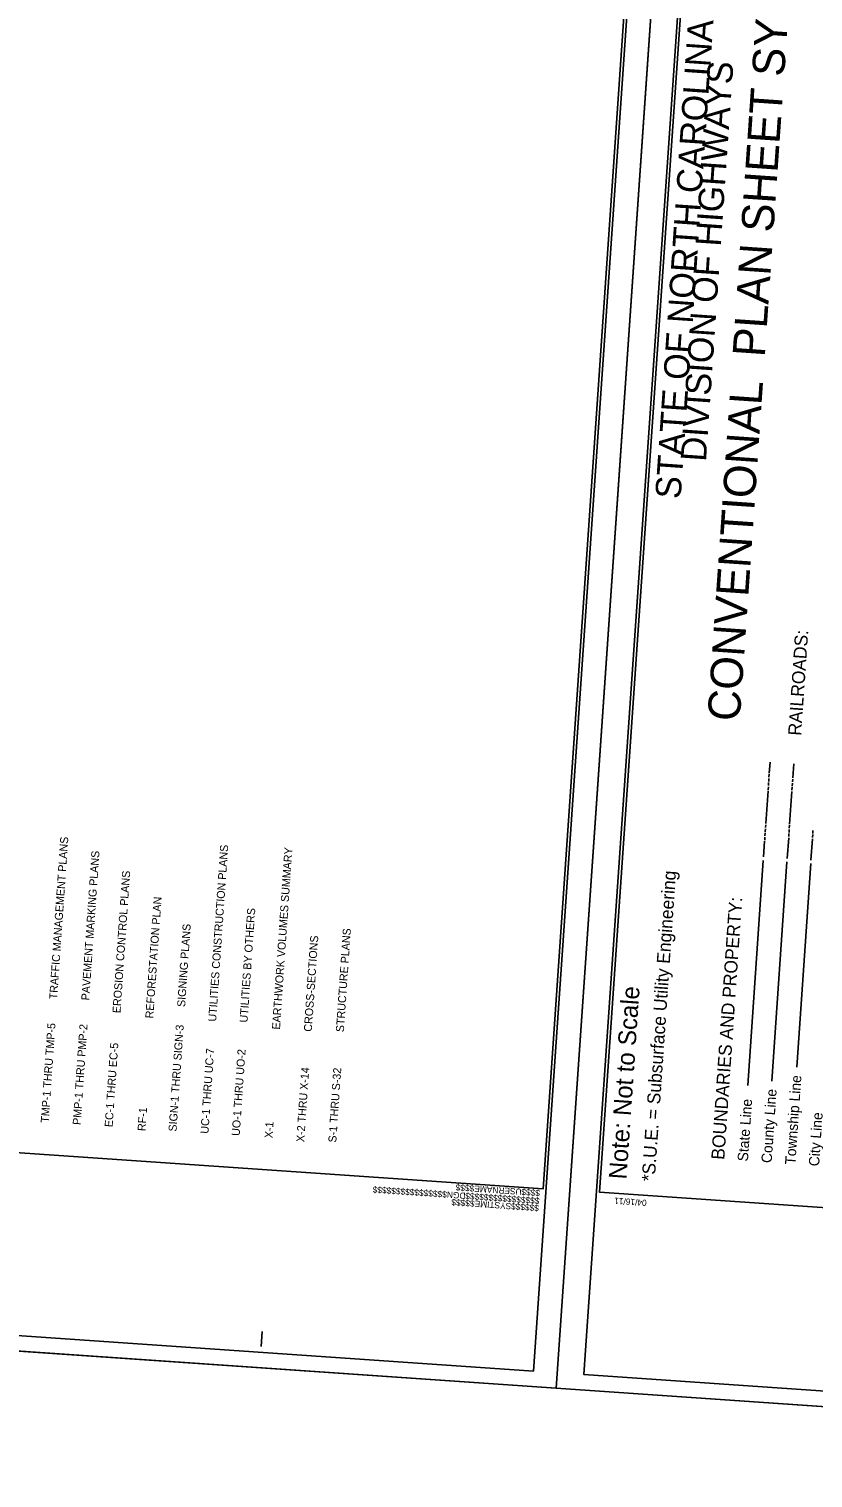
# Model space of a CAD drawing. Extents: x 2598107 to 2605763, y 726018 to 731166.
# Drawn here: x 2602035 to 2603520, y 726877 to 729620 of the extents above; entities that cross this region are included whole.
import ezdxf

# ---------------------------------------------------------------- set-up
doc = ezdxf.new("R2010")
doc.units = 0
for name, color, linetype in [('Prop EOT', 7, 'Continuous'), ('Sheet Cutting Line CELL', 7, 'Continuous'), ('Sheet Plan CELL', 7, 'Continuous'), ('Sheet Plot Border Inside CELL', 7, 'Continuous'), ('Sheet Plot Border Outside CELL', 7, 'Continuous'), ('Sheet Summary Guardrail CELL', 7, 'Continuous'), ('Sheet Symbology CELL', 7, 'Continuous')]:
    doc.layers.add(name, color=color, linetype=linetype)

msp = doc.modelspace()

# ---------------------------------------------------------------- linework, layer by layer
at = {"layer": 'Sheet Cutting Line CELL'}
for p, q in [((2603294, 730826.7), (2603033.6, 727046.7)), ((2603033.6, 727046.7), (2603293.9, 730825.6)), ((2600575.7, 727216), (2603033.6, 727046.7)), ((2603033.6, 727046.7), (2605502.8, 726876.6))]:
    msp.add_line(p, q, dxfattribs=at)
at = {"layer": 'Sheet Plan CELL'}
for p, q in [((2603008.9, 727423.9), (2603008.9, 727423.9)), ((2602475.2, 727125.8), (2602477.2, 727153.8))]:
    msp.add_line(p, q, dxfattribs=at)
msp.add_lwpolyline([(2600883.8, 730953.3), (2600651.9, 727586.2), (2603008.9, 727423.9), (2603240.7, 730790.9)], close=True, dxfattribs=at)
at = {"layer": 'Sheet Plot Border Inside CELL'}
for points in [[(2602990.7, 727079), (2603248.3, 730818.6), (2600880.2, 730981.7), (2600622.6, 727242.1)], [(2605454.4, 726909.3), (2605712, 730650.1), (2603343.7, 730813.2), (2603086, 727072.4)]]:
    msp.add_lwpolyline(points, close=True, dxfattribs=at)
at = {"layer": 'Sheet Plot Border Outside CELL'}
for points in [[(2603033.6, 727046.7), (2603293.9, 730825.6), (2600836, 730994.9), (2600575.7, 727216)], [(2605502.8, 726876.6), (2605763.1, 730656.7), (2603294, 730826.7), (2603033.6, 727046.7)]]:
    msp.add_lwpolyline(points, close=True, dxfattribs=at)
at = {"layer": 'Sheet Symbology CELL'}
for p, q in [((2603437, 728211.3), (2603438.4, 728232.2)), ((2603481.5, 728202.3), (2603483.3, 728229.1)), ((2603435.4, 728187.7), (2603435.7, 728193.3)), ((2603435.9, 728195.6), (2603436.3, 728201.2)), ((2603436.4, 728203.4), (2603436.8, 728209)), ((2603480.9, 728194.5), (2603481.3, 728200.1)), ((2603430.4, 728115.9), (2603434.7, 728177.6)), ((2603434.8, 728179.9), (2603435.2, 728185.5)), ((2603475.4, 728114.8), (2603479.7, 728176.5)), ((2603479.9, 728178.8), (2603480.2, 728184.4)), ((2603480.4, 728186.6), (2603480.8, 728192.2)), ((2603429.9, 728108), (2603430.3, 728113.6)), ((2603474.9, 728106.9), (2603475.3, 728112.5)), ((2603428.3, 728084.5), (2603428.6, 728090.1)), ((2603428.8, 728092.3), (2603429.2, 728097.9)), ((2603429.3, 728100.2), (2603429.7, 728105.8)), ((2603471, 728049.5), (2603473.7, 728089)), ((2603473.8, 728091.2), (2603474.2, 728096.8)), ((2603474.4, 728099.1), (2603474.8, 728104.7)), ((2603515.8, 728046.4), (2603518.6, 728086.9)), ((2603518.8, 728089.2), (2603519.2, 728094.8)), ((2603519.3, 728097), (2603519.7, 728102.6)), ((2603426.1, 728052.6), (2603428.1, 728082.2)), ((2603425.6, 728046.1), (2603396.2, 727619.7)), ((2603470.5, 728043), (2603441.9, 727627.8)), ((2603515.4, 728039.9), (2603488.9, 727654.5))]:
    msp.add_line(p, q, dxfattribs=at)
msp.add_lwpolyline([(2603347.4, 730784.7), (2603115.6, 727417.7), (2605470.2, 727255.5), (2605702.1, 730622.6)], close=True, dxfattribs=at)

# ---------------------------------------------------------------- texts
at = {"layer": 'Prop EOT'}
for s, p in [('TMP-1 THRU TMP-5        TRAFFIC MANAGEMENT PLANS', (2602072.7, 727548.9)), ('PMP-1 THRU PMP-2        PAVEMENT MARKING PLANS', (2602133.2, 727544.7)), ('UC-1 THRU UC-7         UTILITIES CONSTRUCTION PLANS', (2602375.1, 727528.1)), ('X-1                               EARTHWORK VOLUMES SUMMARY ', (2602496.4, 727519.7)), ('EC-1 THRU EC-5          EROSION CONTROL PLANS', (2602193.7, 727540.6)), ('RF-1                              REFORESTATION PLAN', (2602256, 727533)), ('UO-1 THRU UO-2         UTILITIES BY OTHERS', (2602434.3, 727524)), ('SIGN-1 THRU SIGN-3      SIGNING PLANS', (2602314.7, 727532.2)), ('X-2 THRU X-14            CROSS-SECTIONS', (2602556.4, 727512.3)), ('S-1 THRU S-32            STRUCTURE PLANS', (2602617.1, 727511.4))]:
    msp.add_text(s, height=15.156, rotation=86.0601, dxfattribs=at).set_placement(p)
at = {"layer": 'Sheet Plan CELL'}
for s, p in [('$$$$$$$$$$$$$$$$DGN$$$$$$$$$$$$$$$$', (2603002.4, 727407.1)), ('$$$$USERNAME$$$$', (2603003.4, 727421.9)), ('$$$$$$SYSTIME$$$$$', (2603001.4, 727393.5))]:
    msp.add_text(s, height=11.812, rotation=176.0601, dxfattribs=at).set_placement(p)
at = {"layer": 'Sheet Summary Guardrail CELL'}
msp.add_text('04/16/11', height=11.81, rotation=176.0601, dxfattribs=at).set_placement((2603205.2, 727403.3))
at = {"layer": 'Sheet Symbology CELL'}
for s, height, p in [('CONVENTIONAL  PLAN SHEET SYMBOLS', 61.201, (2603380.9, 728308.3)), ('STATE OF NORTH CAROLINA', 48.193, (2603269, 728729.4)), ('DIVISION OF HIGHWAYS', 48.193, (2603317.1, 728800.2)), ('RAILROADS:', 24.75, (2603497.2, 728281.6)), ('*S.U.E. = Subsurface Utility Engineering', 24.75, (2603220.1, 727437.7)), ('BOUNDARIES AND PROPERTY:', 24.75, (2603351.7, 727478.6)), ('Note: Not to Scale', 33.75, (2603166.6, 727441.4)), ('Township Line', 19.688, (2603486.3, 727469.4)), ('State Line', 19.69, (2603396.5, 727475.6)), ('County Line', 19.688, (2603441.4, 727472.5)), ('City Line', 19.69, (2603531.2, 727466.3))]:
    msp.add_text(s, height=height, rotation=86.0601, dxfattribs=at).set_placement(p)

doc.saveas('drawing.dxf')
